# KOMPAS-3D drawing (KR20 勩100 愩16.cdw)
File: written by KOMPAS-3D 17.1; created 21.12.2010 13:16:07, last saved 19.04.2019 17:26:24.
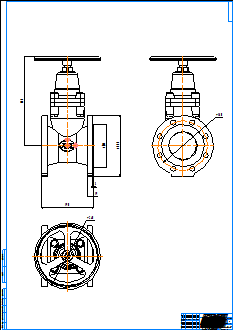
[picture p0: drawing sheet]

Title block, sheet 1: name: KR20 Ду100 Ру16; material: Внимание! Данный продукт является объектом авторского права ООО «Торговый Дом АДЛ». / Запрещается изменение, копирование, распространение / (в том числе путем копирования на другие сайты и ресурсы в Интернете) / или любое иное использование информации и объектов без предварительного / согласия правообладателя (ООО «Торговый Дом АДЛ»).; scale: 1:1; sheets: 1; organisation: ООО "Торговый дом АДЛ"; sheet format: A0; stored path: \\adlc.lan\data\АДЛ_ПКД\3D-модели\ADL production\Клиновые задвижки серии KR ГРАНАР\Клиновые задвижки KR20\KOMPAS 2D\KR20 Ду100 Ру16.cdw

Views: Спереди 1, Проекционный вид 2, Проекционный вид 3
Dimensions and other numbers on the sheet: 3; 19; 190; 153; 220; 320; 180; 240; 1:1; 1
